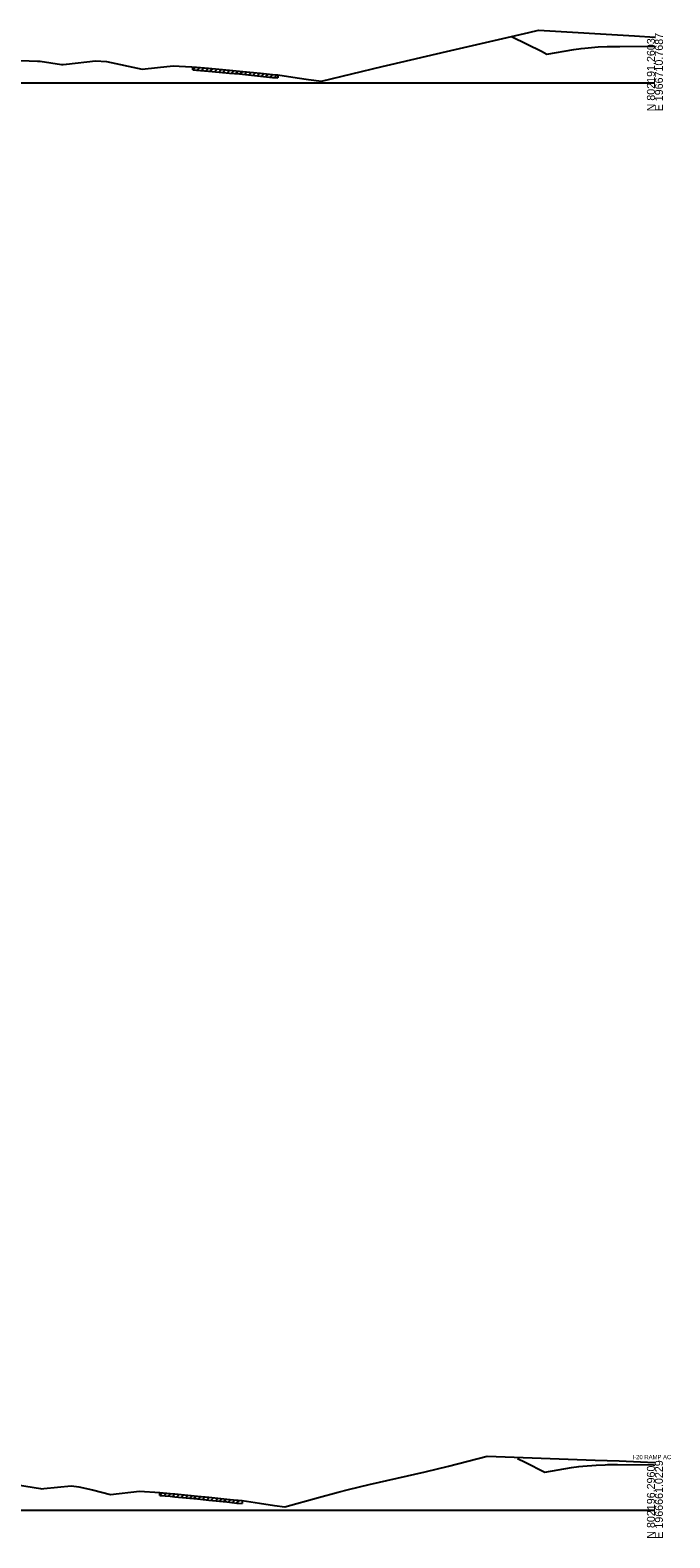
# Model space of a CAD drawing. Extents: x -26 to 1986619, y -10 to 827846.
# Drawn here: x 381 to 605, y 18490 to 19018 of the extents above; entities that cross this region are included whole.
import ezdxf

# ---------------------------------------------------------------- set-up
doc = ezdxf.new("R2010")
doc.units = 0
for name, color, linetype in [('RD_GPK_XS_Cell', 7, 'Continuous'), ('RD_TX_Misc1', 7, 'Continuous'), ('RD_XS_ExGround', 7, 'Continuous'), ('RD_XS_ExPaveRet', 7, 'Continuous'), ('RD_XS_Pave', 7, 'Continuous')]:
    doc.layers.add(name, color=color, linetype=linetype)

msp = doc.modelspace()

# ---------------------------------------------------------------- linework, layer by layer
at = {"layer": 'RD_GPK_XS_Cell'}
for p, q in [((300, 19000), (600, 19000)), ((300, 18500), (600, 18500))]:
    msp.add_line(p, q, dxfattribs=at)
at = {"layer": 'RD_XS_ExGround'}
for points in [[(374.9, 19007.98), (383.79, 19007.59), (384.69, 19007.55), (392.2, 19006.45), (392.81, 19006.36), (393.96, 19006.51), (404.07, 19007.71), (407.89, 19007.46), (420.46, 19004.73), (425.86, 19005.35), (431.25, 19005.92), (437.76, 19005.57), (438.23, 19005.54), (439.47, 19005.44), (443.68, 19005.08), (450.96, 19004.42), (454.57, 19004.1), (461.89, 19003.33), (466.1, 19002.92), (467.03, 19002.84), (467.99, 19002.76), (474.74, 19001.78), (478.64, 19001.21), (483.25, 19000.54), (504.44, 19005.74), (507.55, 19006.45), (527, 19010.94), (555.82, 19017.64), (559.24, 19018.45), (592.87, 19016.47), (600, 19016.04)], [(376.73, 18508.84), (384.78, 18507.55), (385.26, 18507.48), (386.03, 18507.57), (395.6, 18508.56), (397.39, 18508.35), (398.31, 18508.23), (403.06, 18507.1), (409.31, 18505.52), (419.49, 18506.69), (426.57, 18506.18), (430.22, 18505.85), (431.87, 18505.71), (439.84, 18504.93), (443.81, 18504.55), (450.03, 18503.89), (453.64, 18503.51), (454.07, 18503.47), (455.47, 18503.34), (461.47, 18502.44), (466.8, 18501.66), (470.35, 18501.12), (482.24, 18504.39), (489.1, 18506.27), (492.64, 18507.21), (499.9, 18508.94), (519.49, 18513.42), (527.73, 18515.44), (541.22, 18518.87), (579.11, 18517.56), (587.46, 18517.29), (594.92, 18516.9), (600, 18516.72)]]:
    msp.add_lwpolyline(points, dxfattribs=at)
at = {"layer": 'RD_XS_ExPaveRet'}
for p, q in [((438.23, 19004.54), (438.23, 19005.54)), ((438.23, 19004.54), (439.15, 19005.46)), ((438.23, 19004.54), (439.47, 19004.44)), ((439.47, 19004.44), (443.68, 19004.08)), ((439.73, 19004.41), (440.65, 19005.34)), ((441.23, 19004.29), (442.15, 19005.21)), ((442.73, 19004.16), (443.65, 19005.08)), ((443.68, 19004.08), (450.96, 19003.42)), ((444.23, 19004.03), (445.14, 19004.95)), ((445.73, 19003.89), (446.64, 19004.81)), ((447.23, 19003.76), (448.14, 19004.68)), ((448.73, 19003.62), (449.64, 19004.54)), ((450.23, 19003.49), (451.15, 19004.4)), ((450.96, 19003.42), (454.57, 19003.1)), ((451.73, 19003.35), (452.65, 19004.27)), ((453.23, 19003.22), (454.15, 19004.14)), ((454.57, 19003.1), (461.89, 19002.33)), ((454.73, 19003.09), (455.63, 19003.99)), ((456.23, 19002.93), (457.13, 19003.83)), ((457.73, 19002.77), (458.63, 19003.68)), ((459.23, 19002.61), (460.13, 19003.52)), ((460.73, 19002.46), (461.63, 19003.36)), ((462.23, 19002.3), (463.14, 19003.21)), ((463.73, 19002.16), (464.64, 19003.07)), ((465.23, 19002.01), (466.14, 19002.92)), ((466.73, 19001.87), (467.65, 19002.79)), ((467.99, 19002.76), (467.99, 19001.76)), ((461.89, 19002.33), (466.1, 19001.92)), ((466.1, 19001.92), (467.03, 19001.84)), ((467.03, 19001.84), (467.99, 19001.76)), ((426.57, 18505.18), (426.57, 18506.18)), ((426.57, 18505.18), (427.49, 18506.1)), ((426.57, 18505.18), (430.22, 18504.85)), ((428.07, 18505.05), (428.99, 18505.96)), ((429.57, 18504.91), (430.49, 18505.83)), ((430.22, 18504.85), (431.87, 18504.71)), ((431.07, 18504.78), (431.99, 18505.69)), ((431.87, 18504.71), (439.84, 18503.93)), ((432.57, 18504.64), (433.48, 18505.55)), ((434.07, 18504.49), (434.98, 18505.4)), ((435.57, 18504.34), (436.48, 18505.25)), ((437.07, 18504.2), (437.98, 18505.11)), ((438.57, 18504.05), (439.48, 18504.96)), ((439.84, 18503.93), (443.81, 18503.55)), ((440.07, 18503.9), (440.98, 18504.82)), ((441.57, 18503.76), (442.48, 18504.68)), ((443.07, 18503.62), (443.98, 18504.53)), ((443.81, 18503.55), (450.03, 18502.89)), ((444.57, 18503.47), (445.47, 18504.37)), ((446.07, 18503.31), (446.97, 18504.22)), ((447.57, 18503.15), (448.47, 18504.06)), ((449.07, 18502.99), (449.97, 18503.9)), ((450.03, 18502.89), (453.64, 18502.51)), ((450.57, 18502.84), (451.47, 18503.74)), ((452.07, 18502.68), (452.97, 18503.58)), ((453.57, 18502.52), (454.48, 18503.43)), ((453.64, 18502.51), (454.07, 18502.47)), ((454.07, 18502.47), (455.47, 18502.34)), ((455.47, 18503.34), (455.47, 18502.34))]:
    msp.add_line(p, q, dxfattribs=at)
at = {"layer": 'RD_XS_Pave'}
for points in [[(550.02, 19016.16), (560.23, 19011.05), (562.16, 19010.09), (571.56, 19011.65), (574.16, 19012.08), (575.47, 19012.18), (580.16, 19012.55), (583.28, 19012.68), (584.16, 19012.71), (587.71, 19012.78), (600, 19012.85)], [(551.82, 18518.14), (554.56, 18516.77), (561.4, 18513.35), (570.8, 18514.91), (573.4, 18515.34), (574.71, 18515.44), (579.4, 18515.81), (582.52, 18515.94), (583.4, 18515.97), (586.95, 18515.99), (599.41, 18515.85), (600, 18515.82)]]:
    msp.add_lwpolyline(points, dxfattribs=at)

# ---------------------------------------------------------------- texts
at = {"layer": 'RD_GPK_XS_Cell'}
for s, p in [('N 802191.2603', (600, 18990)), ('E 1966710.7687', (602.8, 18990)), ('E 1966661.0229', (602.8, 18490)), ('N 802196.2960', (600, 18490))]:
    msp.add_text(s, height=2.8, rotation=90, dxfattribs=at).set_placement(p)
at = {"layer": 'RD_TX_Misc1'}
msp.add_text('I-20 RAMP AC', height=1.5, dxfattribs=at).set_placement((592.15, 18517.85))

doc.saveas('drawing.dxf')
